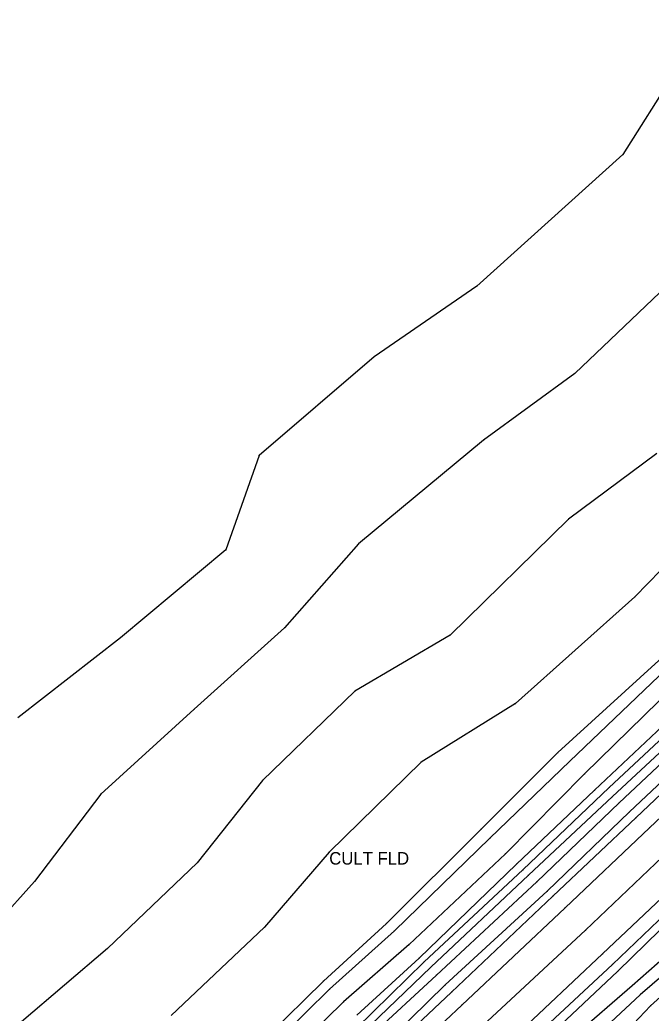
# Model space of a CAD drawing. Extents: x 1419505 to 1434054, y 1956910 to 1968644.
# Drawn here: x 1433102.4 to 1433354.9, y 1967820.7 to 1968218.1 of the extents above; entities that cross this region are included whole.
import ezdxf

# ---------------------------------------------------------------- set-up
doc = ezdxf.new("R2010")
doc.units = 0
for name, color, linetype in [('S_BREAKLINE', 7, 'Continuous'), ('S_DITCHLINE', 7, 'Continuous'), ('S_EDGE_PAVEMENT', 7, 'Continuous'), ('S_GRD_PT_SYM', 7, 'Continuous'), ('S_MSC_PT_SYM', 7, 'Continuous'), ('S_PAVEMENT_CROWN', 7, 'Continuous'), ('S_RDW_PT_SYM', 7, 'Continuous'), ('S_SHOULDER', 7, 'Continuous'), ('S_SURVEY_TEXT_ANNOT', 7, 'Continuous')]:
    doc.layers.add(name, color=color, linetype=linetype)

msp = doc.modelspace()

# ---------------------------------------------------------------- linework, layer by layer
at = {"layer": 'S_BREAKLINE'}
for p, q in [((1433377.4761, 1968218.0776), (1433343.6299, 1968164.1561)), ((1433343.6299, 1968164.1561), (1433285.2201, 1968111.5567)), ((1433372.3288, 1968122.4084), (1433324.3727, 1968076.6374)), ((1433285.2201, 1968111.5567), (1433244.1035, 1968083.3359)), ((1433244.1035, 1968083.3359), (1433198.2095, 1968043.8323)), ((1433324.3727, 1968076.6374), (1433287.8633, 1968049.8817)), ((1433287.8633, 1968049.8817), (1433237.8061, 1968008.441)), ((1433198.2095, 1968043.8323), (1433184.8366, 1968006.0259)), ((1433357.1698, 1968044.5593), (1433321.8795, 1968018.3507)), ((1433381.3473, 1968021.4289), (1433348.4512, 1967987.2566)), ((1433321.8795, 1968018.3507), (1433274.4954, 1967971.9817)), ((1433237.8061, 1968008.441), (1433208.2482, 1967974.8618)), ((1433184.8366, 1968006.0259), (1433142.6609, 1967970.8926)), ((1433348.4512, 1967987.2566), (1433300.7111, 1967944.5899)), ((1433208.2482, 1967974.8618), (1433172.1358, 1967942.2717)), ((1433274.4954, 1967971.9817), (1433236.462, 1967949.5352)), ((1433142.6609, 1967970.8926), (1433101.6873, 1967938.8085)), ((1433366.0013, 1967969.1485), (1433317.6282, 1967925.0046)), ((1433369.0245, 1967966.1193), (1433322.3975, 1967921.5484)), ((1433374.0349, 1967961.366), (1433328.2779, 1967916.4151)), ((1433380.4183, 1967955.4326), (1433332.3222, 1967909.8727)), ((1433236.462, 1967949.5352), (1433199.4326, 1967913.7389)), ((1433388.6688, 1967948.7392), (1433342.1288, 1967904.9293)), ((1433300.7111, 1967944.5899), (1433262.9267, 1967921.1794)), ((1433391.915, 1967944.5839), (1433346.3081, 1967901.2751)), ((1433172.1358, 1967942.2717), (1433134.7944, 1967908.3576)), ((1433317.6282, 1967925.0046), (1433286.9092, 1967894.2976)), ((1433262.9267, 1967921.1794), (1433226.1713, 1967885.1601)), ((1433322.3975, 1967921.5484), (1433290.4185, 1967890.7124)), ((1433328.2779, 1967916.4151), (1433296.6219, 1967884.508)), ((1433199.4326, 1967913.7389), (1433173.3439, 1967880.8768)), ((1433134.7944, 1967908.3576), (1433108.2867, 1967873.3333)), ((1433332.3222, 1967909.8727), (1433300.9981, 1967880.3407)), ((1433342.1288, 1967904.9293), (1433309.2207, 1967873.2893)), ((1433346.3081, 1967901.2751), (1433313.3629, 1967869.469)), ((1433286.9092, 1967894.2976), (1433249.0298, 1967856.6152)), ((1433290.4185, 1967890.7124), (1433252.272, 1967853.717)), ((1433226.1713, 1967885.1601), (1433200.3416, 1967855.1111)), ((1433296.6219, 1967884.508), (1433258.1904, 1967848.1787)), ((1433173.3439, 1967880.8768), (1433137.4226, 1967846.5776)), ((1433300.9981, 1967880.3407), (1433262.1536, 1967842.7623)), ((1433108.2867, 1967873.3333), (1433085.1902, 1967847.7066)), ((1433309.2207, 1967873.2893), (1433269.0291, 1967835.9779)), ((1433313.3629, 1967869.469), (1433272.5963, 1967831.9996)), ((1433376.682, 1967872.0092), (1433341.5898, 1967837.497)), ((1433389.4409, 1967868.772), (1433347.3031, 1967831.6846)), ((1433200.3416, 1967855.1111), (1433162.9732, 1967819.7808)), ((1433249.0298, 1967856.6152), (1433223.8082, 1967833.5837)), ((1433252.272, 1967853.717), (1433226.3333, 1967830.2745)), ((1433137.4226, 1967846.5776), (1433103.1444, 1967817.3197)), ((1433258.1904, 1967848.1787), (1433231.9147, 1967825.2392)), ((1433262.1536, 1967842.7623), (1433237.159, 1967819.8888)), ((1433341.5898, 1967837.497), (1433301.9652, 1967800.2766)), ((1433223.8082, 1967833.5837), (1433186.5128, 1967796.8904)), ((1433269.0291, 1967835.9779), (1433241.2773, 1967810.3682)), ((1433226.3333, 1967830.2745), (1433189.1059, 1967793.8502)), ((1433272.5963, 1967831.9996), (1433246.4166, 1967806.522)), ((1433347.3031, 1967831.6846), (1433305.7615, 1967795.7433)), ((1433231.9147, 1967825.2392), (1433196.1504, 1967790.3909))]:
    msp.add_line(p, q, dxfattribs=at)
at = {"layer": 'S_DITCHLINE'}
for p, q in [((1433383.1975, 1967953.1234), (1433338.1335, 1967910.9367)), ((1433386.0926, 1967950.9283), (1433339.4866, 1967907.3875)), ((1433338.1335, 1967910.9367), (1433303.6153, 1967878.0406)), ((1433339.4866, 1967907.3875), (1433305.9285, 1967875.9555)), ((1433303.6153, 1967878.0406), (1433264.0878, 1967841.2452)), ((1433305.9285, 1967875.9555), (1433266.7869, 1967839.1381)), ((1433392.5861, 1967864.4477), (1433350.4883, 1967828.0614)), ((1433395.8103, 1967860.7865), (1433354.6046, 1967823.5971)), ((1433264.0878, 1967841.2452), (1433236.969, 1967814.5745)), ((1433266.7869, 1967839.1381), (1433239.2612, 1967812.6364)), ((1433350.4883, 1967828.0614), (1433309.1797, 1967789.6279)), ((1433354.6046, 1967823.5971), (1433316.6672, 1967783.7655))]:
    msp.add_line(p, q, dxfattribs=at)
at = {"layer": 'S_EDGE_PAVEMENT'}
for p, q in [((1433399.6665, 1967938.1975), (1433354.2296, 1967894.8497)), ((1433354.2296, 1967894.8497), (1433320.4914, 1967862.8816)), ((1433370.7557, 1967877.9586), (1433335.4914, 1967844.4224)), ((1433320.4914, 1967862.8816), (1433279.1627, 1967823.9671)), ((1433335.4914, 1967844.4224), (1433295.3648, 1967806.742)), ((1433279.1627, 1967823.9671), (1433253.037, 1967799.2915))]:
    msp.add_line(p, q, dxfattribs=at)
at = {"layer": 'S_GRD_PT_SYM'}
for points in [[(1433343.6299, 1968164.1561), (1433343.6299, 1968164.2061), (1433343.6299, 1968164.1561), (1433343.5799, 1968164.1561), (1433343.6299, 1968164.1561), (1433343.6299, 1968164.1061), (1433343.6299, 1968164.1561), (1433343.6799, 1968164.1561)], [(1433285.2201, 1968111.5567), (1433285.2201, 1968111.6067), (1433285.2201, 1968111.5567), (1433285.1701, 1968111.5567), (1433285.2201, 1968111.5567), (1433285.2201, 1968111.5067), (1433285.2201, 1968111.5567), (1433285.2701, 1968111.5567)], [(1433244.1035, 1968083.3359), (1433244.1035, 1968083.3859), (1433244.1035, 1968083.3359), (1433244.0535, 1968083.3359), (1433244.1035, 1968083.3359), (1433244.1035, 1968083.2859), (1433244.1035, 1968083.3359), (1433244.1535, 1968083.3359)], [(1433324.3727, 1968076.6374), (1433324.3727, 1968076.6874), (1433324.3727, 1968076.6374), (1433324.3227, 1968076.6374), (1433324.3727, 1968076.6374), (1433324.3727, 1968076.5874), (1433324.3727, 1968076.6374), (1433324.4227, 1968076.6374)], [(1433287.8633, 1968049.8817), (1433287.8633, 1968049.9317), (1433287.8633, 1968049.8817), (1433287.8133, 1968049.8817), (1433287.8633, 1968049.8817), (1433287.8633, 1968049.8317), (1433287.8633, 1968049.8817), (1433287.9133, 1968049.8817)], [(1433198.2095, 1968043.8323), (1433198.2095, 1968043.8823), (1433198.2095, 1968043.8323), (1433198.1595, 1968043.8323), (1433198.2095, 1968043.8323), (1433198.2095, 1968043.7823), (1433198.2095, 1968043.8323), (1433198.2595, 1968043.8323)], [(1433321.8795, 1968018.3507), (1433321.8795, 1968018.4007), (1433321.8795, 1968018.3507), (1433321.8295, 1968018.3507), (1433321.8795, 1968018.3507), (1433321.8795, 1968018.3007), (1433321.8795, 1968018.3507), (1433321.9295, 1968018.3507)], [(1433237.8061, 1968008.441), (1433237.8061, 1968008.491), (1433237.8061, 1968008.441), (1433237.7561, 1968008.441), (1433237.8061, 1968008.441), (1433237.8061, 1968008.391), (1433237.8061, 1968008.441), (1433237.8561, 1968008.441)], [(1433184.8366, 1968006.0259), (1433184.8366, 1968006.0759), (1433184.8366, 1968006.0259), (1433184.7866, 1968006.0259), (1433184.8366, 1968006.0259), (1433184.8366, 1968005.9759), (1433184.8366, 1968006.0259), (1433184.8866, 1968006.0259)], [(1433348.4512, 1967987.2566), (1433348.4512, 1967987.3066), (1433348.4512, 1967987.2566), (1433348.4012, 1967987.2566), (1433348.4512, 1967987.2566), (1433348.4512, 1967987.2066), (1433348.4512, 1967987.2566), (1433348.5012, 1967987.2566)], [(1433208.2482, 1967974.8618), (1433208.2482, 1967974.9118), (1433208.2482, 1967974.8618), (1433208.1982, 1967974.8618), (1433208.2482, 1967974.8618), (1433208.2482, 1967974.8118), (1433208.2482, 1967974.8618), (1433208.2982, 1967974.8618)], [(1433274.4954, 1967971.9817), (1433274.4954, 1967972.0317), (1433274.4954, 1967971.9817), (1433274.4454, 1967971.9817), (1433274.4954, 1967971.9817), (1433274.4954, 1967971.9317), (1433274.4954, 1967971.9817), (1433274.5454, 1967971.9817)], [(1433142.6609, 1967970.8926), (1433142.6609, 1967970.9426), (1433142.6609, 1967970.8926), (1433142.6109, 1967970.8926), (1433142.6609, 1967970.8926), (1433142.6609, 1967970.8426), (1433142.6609, 1967970.8926), (1433142.7109, 1967970.8926)], [(1433236.462, 1967949.5352), (1433236.462, 1967949.5852), (1433236.462, 1967949.5352), (1433236.412, 1967949.5352), (1433236.462, 1967949.5352), (1433236.462, 1967949.4852), (1433236.462, 1967949.5352), (1433236.512, 1967949.5352)], [(1433300.7111, 1967944.5899), (1433300.7111, 1967944.6399), (1433300.7111, 1967944.5899), (1433300.6611, 1967944.5899), (1433300.7111, 1967944.5899), (1433300.7111, 1967944.5399), (1433300.7111, 1967944.5899), (1433300.7611, 1967944.5899)], [(1433172.1358, 1967942.2717), (1433172.1358, 1967942.3217), (1433172.1358, 1967942.2717), (1433172.0858, 1967942.2717), (1433172.1358, 1967942.2717), (1433172.1358, 1967942.2217), (1433172.1358, 1967942.2717), (1433172.1858, 1967942.2717)], [(1433317.6282, 1967925.0046), (1433317.6282, 1967925.0546), (1433317.6282, 1967925.0046), (1433317.5782, 1967925.0046), (1433317.6282, 1967925.0046), (1433317.6282, 1967924.9546), (1433317.6282, 1967925.0046), (1433317.6782, 1967925.0046)], [(1433262.9267, 1967921.1794), (1433262.9267, 1967921.2294), (1433262.9267, 1967921.1794), (1433262.8767, 1967921.1794), (1433262.9267, 1967921.1794), (1433262.9267, 1967921.1294), (1433262.9267, 1967921.1794), (1433262.9767, 1967921.1794)], [(1433322.3975, 1967921.5484), (1433322.3975, 1967921.5984), (1433322.3975, 1967921.5484), (1433322.3475, 1967921.5484), (1433322.3975, 1967921.5484), (1433322.3975, 1967921.4984), (1433322.3975, 1967921.5484), (1433322.4475, 1967921.5484)], [(1433328.2779, 1967916.4151), (1433328.2779, 1967916.4651), (1433328.2779, 1967916.4151), (1433328.2279, 1967916.4151), (1433328.2779, 1967916.4151), (1433328.2779, 1967916.3651), (1433328.2779, 1967916.4151), (1433328.3279, 1967916.4151)], [(1433199.4326, 1967913.7389), (1433199.4326, 1967913.7889), (1433199.4326, 1967913.7389), (1433199.3826, 1967913.7389), (1433199.4326, 1967913.7389), (1433199.4326, 1967913.6889), (1433199.4326, 1967913.7389), (1433199.4826, 1967913.7389)], [(1433134.7944, 1967908.3576), (1433134.7944, 1967908.4076), (1433134.7944, 1967908.3576), (1433134.7444, 1967908.3576), (1433134.7944, 1967908.3576), (1433134.7944, 1967908.3076), (1433134.7944, 1967908.3576), (1433134.8444, 1967908.3576)], [(1433332.3222, 1967909.8727), (1433332.3222, 1967909.9227), (1433332.3222, 1967909.8727), (1433332.2722, 1967909.8727), (1433332.3222, 1967909.8727), (1433332.3222, 1967909.8227), (1433332.3222, 1967909.8727), (1433332.3722, 1967909.8727)], [(1433338.1335, 1967910.9367), (1433338.1335, 1967910.9867), (1433338.1335, 1967910.9367), (1433338.0835, 1967910.9367), (1433338.1335, 1967910.9367), (1433338.1335, 1967910.8867), (1433338.1335, 1967910.9367), (1433338.1835, 1967910.9367)], [(1433339.4866, 1967907.3875), (1433339.4866, 1967907.4375), (1433339.4866, 1967907.3875), (1433339.4366, 1967907.3875), (1433339.4866, 1967907.3875), (1433339.4866, 1967907.3375), (1433339.4866, 1967907.3875), (1433339.5366, 1967907.3875)], [(1433342.1288, 1967904.9293), (1433342.1288, 1967904.9793), (1433342.1288, 1967904.9293), (1433342.0788, 1967904.9293), (1433342.1288, 1967904.9293), (1433342.1288, 1967904.8793), (1433342.1288, 1967904.9293), (1433342.1788, 1967904.9293)], [(1433346.3081, 1967901.2751), (1433346.3081, 1967901.3251), (1433346.3081, 1967901.2751), (1433346.2581, 1967901.2751), (1433346.3081, 1967901.2751), (1433346.3081, 1967901.2251), (1433346.3081, 1967901.2751), (1433346.3581, 1967901.2751)], [(1433286.9092, 1967894.2976), (1433286.9092, 1967894.3476), (1433286.9092, 1967894.2976), (1433286.8592, 1967894.2976), (1433286.9092, 1967894.2976), (1433286.9092, 1967894.2476), (1433286.9092, 1967894.2976), (1433286.9592, 1967894.2976)], [(1433290.4185, 1967890.7124), (1433290.4185, 1967890.7624), (1433290.4185, 1967890.7124), (1433290.3685, 1967890.7124), (1433290.4185, 1967890.7124), (1433290.4185, 1967890.6624), (1433290.4185, 1967890.7124), (1433290.4685, 1967890.7124)], [(1433226.1713, 1967885.1601), (1433226.1713, 1967885.2101), (1433226.1713, 1967885.1601), (1433226.1213, 1967885.1601), (1433226.1713, 1967885.1601), (1433226.1713, 1967885.1101), (1433226.1713, 1967885.1601), (1433226.2213, 1967885.1601)], [(1433296.6219, 1967884.508), (1433296.6219, 1967884.558), (1433296.6219, 1967884.508), (1433296.5719, 1967884.508), (1433296.6219, 1967884.508), (1433296.6219, 1967884.458), (1433296.6219, 1967884.508), (1433296.6719, 1967884.508)], [(1433173.3439, 1967880.8768), (1433173.3439, 1967880.9268), (1433173.3439, 1967880.8768), (1433173.2939, 1967880.8768), (1433173.3439, 1967880.8768), (1433173.3439, 1967880.8268), (1433173.3439, 1967880.8768), (1433173.3939, 1967880.8768)], [(1433300.9981, 1967880.3407), (1433300.9981, 1967880.3907), (1433300.9981, 1967880.3407), (1433300.9481, 1967880.3407), (1433300.9981, 1967880.3407), (1433300.9981, 1967880.2907), (1433300.9981, 1967880.3407), (1433301.0481, 1967880.3407)], [(1433303.6153, 1967878.0406), (1433303.6153, 1967878.0906), (1433303.6153, 1967878.0406), (1433303.5653, 1967878.0406), (1433303.6153, 1967878.0406), (1433303.6153, 1967877.9906), (1433303.6153, 1967878.0406), (1433303.6653, 1967878.0406)], [(1433108.2867, 1967873.3333), (1433108.2867, 1967873.3833), (1433108.2867, 1967873.3333), (1433108.2367, 1967873.3333), (1433108.2867, 1967873.3333), (1433108.2867, 1967873.2833), (1433108.2867, 1967873.3333), (1433108.3367, 1967873.3333)], [(1433305.9285, 1967875.9555), (1433305.9285, 1967876.0055), (1433305.9285, 1967875.9555), (1433305.8785, 1967875.9555), (1433305.9285, 1967875.9555), (1433305.9285, 1967875.9055), (1433305.9285, 1967875.9555), (1433305.9785, 1967875.9555)], [(1433309.2207, 1967873.2893), (1433309.2207, 1967873.3393), (1433309.2207, 1967873.2893), (1433309.1707, 1967873.2893), (1433309.2207, 1967873.2893), (1433309.2207, 1967873.2393), (1433309.2207, 1967873.2893), (1433309.2707, 1967873.2893)], [(1433313.3629, 1967869.469), (1433313.3629, 1967869.519), (1433313.3629, 1967869.469), (1433313.3129, 1967869.469), (1433313.3629, 1967869.469), (1433313.3629, 1967869.419), (1433313.3629, 1967869.469), (1433313.4129, 1967869.469)], [(1433249.0298, 1967856.6152), (1433249.0298, 1967856.6652), (1433249.0298, 1967856.6152), (1433248.9798, 1967856.6152), (1433249.0298, 1967856.6152), (1433249.0298, 1967856.5652), (1433249.0298, 1967856.6152), (1433249.0798, 1967856.6152)], [(1433200.3416, 1967855.1111), (1433200.3416, 1967855.1611), (1433200.3416, 1967855.1111), (1433200.2916, 1967855.1111), (1433200.3416, 1967855.1111), (1433200.3416, 1967855.0611), (1433200.3416, 1967855.1111), (1433200.3916, 1967855.1111)], [(1433252.272, 1967853.717), (1433252.272, 1967853.767), (1433252.272, 1967853.717), (1433252.222, 1967853.717), (1433252.272, 1967853.717), (1433252.272, 1967853.667), (1433252.272, 1967853.717), (1433252.322, 1967853.717)], [(1433137.4226, 1967846.5776), (1433137.4226, 1967846.6276), (1433137.4226, 1967846.5776), (1433137.3726, 1967846.5776), (1433137.4226, 1967846.5776), (1433137.4226, 1967846.5276), (1433137.4226, 1967846.5776), (1433137.4726, 1967846.5776)], [(1433258.1904, 1967848.1787), (1433258.1904, 1967848.2287), (1433258.1904, 1967848.1787), (1433258.1404, 1967848.1787), (1433258.1904, 1967848.1787), (1433258.1904, 1967848.1287), (1433258.1904, 1967848.1787), (1433258.2404, 1967848.1787)], [(1433262.1536, 1967842.7623), (1433262.1536, 1967842.8123), (1433262.1536, 1967842.7623), (1433262.1036, 1967842.7623), (1433262.1536, 1967842.7623), (1433262.1536, 1967842.7123), (1433262.1536, 1967842.7623), (1433262.2036, 1967842.7623)], [(1433264.0878, 1967841.2452), (1433264.0878, 1967841.2952), (1433264.0878, 1967841.2452), (1433264.0378, 1967841.2452), (1433264.0878, 1967841.2452), (1433264.0878, 1967841.1952), (1433264.0878, 1967841.2452), (1433264.1378, 1967841.2452)], [(1433266.7869, 1967839.1381), (1433266.7869, 1967839.1881), (1433266.7869, 1967839.1381), (1433266.7369, 1967839.1381), (1433266.7869, 1967839.1381), (1433266.7869, 1967839.0881), (1433266.7869, 1967839.1381), (1433266.8369, 1967839.1381)], [(1433341.5898, 1967837.497), (1433341.5898, 1967837.547), (1433341.5898, 1967837.497), (1433341.5398, 1967837.497), (1433341.5898, 1967837.497), (1433341.5898, 1967837.447), (1433341.5898, 1967837.497), (1433341.6398, 1967837.497)], [(1433223.8082, 1967833.5837), (1433223.8082, 1967833.6337), (1433223.8082, 1967833.5837), (1433223.7582, 1967833.5837), (1433223.8082, 1967833.5837), (1433223.8082, 1967833.5337), (1433223.8082, 1967833.5837), (1433223.8582, 1967833.5837)], [(1433269.0291, 1967835.9779), (1433269.0291, 1967836.0279), (1433269.0291, 1967835.9779), (1433268.9791, 1967835.9779), (1433269.0291, 1967835.9779), (1433269.0291, 1967835.9279), (1433269.0291, 1967835.9779), (1433269.0791, 1967835.9779)], [(1433226.3333, 1967830.2745), (1433226.3333, 1967830.3245), (1433226.3333, 1967830.2745), (1433226.2833, 1967830.2745), (1433226.3333, 1967830.2745), (1433226.3333, 1967830.2245), (1433226.3333, 1967830.2745), (1433226.3833, 1967830.2745)], [(1433272.5963, 1967831.9996), (1433272.5963, 1967832.0496), (1433272.5963, 1967831.9996), (1433272.5463, 1967831.9996), (1433272.5963, 1967831.9996), (1433272.5963, 1967831.9496), (1433272.5963, 1967831.9996), (1433272.6463, 1967831.9996)], [(1433347.3031, 1967831.6846), (1433347.3031, 1967831.7346), (1433347.3031, 1967831.6846), (1433347.2531, 1967831.6846), (1433347.3031, 1967831.6846), (1433347.3031, 1967831.6346), (1433347.3031, 1967831.6846), (1433347.3531, 1967831.6846)], [(1433231.9147, 1967825.2392), (1433231.9147, 1967825.2892), (1433231.9147, 1967825.2392), (1433231.8647, 1967825.2392), (1433231.9147, 1967825.2392), (1433231.9147, 1967825.1892), (1433231.9147, 1967825.2392), (1433231.9647, 1967825.2392)], [(1433350.4883, 1967828.0614), (1433350.4883, 1967828.1114), (1433350.4883, 1967828.0614), (1433350.4383, 1967828.0614), (1433350.4883, 1967828.0614), (1433350.4883, 1967828.0114), (1433350.4883, 1967828.0614), (1433350.5383, 1967828.0614)], [(1433354.6046, 1967823.5971), (1433354.6046, 1967823.6471), (1433354.6046, 1967823.5971), (1433354.5546, 1967823.5971), (1433354.6046, 1967823.5971), (1433354.6046, 1967823.5471), (1433354.6046, 1967823.5971), (1433354.6546, 1967823.5971)]]:
    msp.add_lwpolyline(points, dxfattribs=at)
at = {"layer": 'S_MSC_PT_SYM'}
msp.add_lwpolyline([(1433226.1713, 1967885.1601), (1433226.1713, 1967885.2101), (1433226.1713, 1967885.1601), (1433226.1213, 1967885.1601), (1433226.1713, 1967885.1601), (1433226.1713, 1967885.1101), (1433226.1713, 1967885.1601), (1433226.2213, 1967885.1601)], dxfattribs=at)
at = {"layer": 'S_PAVEMENT_CROWN'}
for p, q in [((1433362.3101, 1967885.9091), (1433328.6849, 1967853.869)), ((1433328.6849, 1967853.869), (1433287.6343, 1967815.8096))]:
    msp.add_line(p, q, dxfattribs=at)
at = {"layer": 'S_RDW_PT_SYM'}
for points in [[(1433348.9792, 1967899.06), (1433348.9792, 1967899.11), (1433348.9792, 1967899.06), (1433348.9292, 1967899.06), (1433348.9792, 1967899.06), (1433348.9792, 1967899.01), (1433348.9792, 1967899.06), (1433349.0292, 1967899.06)], [(1433354.2296, 1967894.8497), (1433354.2296, 1967894.8997), (1433354.2296, 1967894.8497), (1433354.1796, 1967894.8497), (1433354.2296, 1967894.8497), (1433354.2296, 1967894.7997), (1433354.2296, 1967894.8497), (1433354.2796, 1967894.8497)], [(1433315.6171, 1967867.5559), (1433315.6171, 1967867.6059), (1433315.6171, 1967867.5559), (1433315.5671, 1967867.5559), (1433315.6171, 1967867.5559), (1433315.6171, 1967867.5059), (1433315.6171, 1967867.5559), (1433315.6671, 1967867.5559)], [(1433320.4914, 1967862.8816), (1433320.4914, 1967862.9316), (1433320.4914, 1967862.8816), (1433320.4414, 1967862.8816), (1433320.4914, 1967862.8816), (1433320.4914, 1967862.8316), (1433320.4914, 1967862.8816), (1433320.5414, 1967862.8816)], [(1433328.6849, 1967853.869), (1433328.6849, 1967853.919), (1433328.6849, 1967853.869), (1433328.6349, 1967853.869), (1433328.6849, 1967853.869), (1433328.6849, 1967853.819), (1433328.6849, 1967853.869), (1433328.7349, 1967853.869)], [(1433335.4914, 1967844.4224), (1433335.4914, 1967844.4724), (1433335.4914, 1967844.4224), (1433335.4414, 1967844.4224), (1433335.4914, 1967844.4224), (1433335.4914, 1967844.3724), (1433335.4914, 1967844.4224), (1433335.5414, 1967844.4224)], [(1433339.4096, 1967840.2142), (1433339.4096, 1967840.2642), (1433339.4096, 1967840.2142), (1433339.3596, 1967840.2142), (1433339.4096, 1967840.2142), (1433339.4096, 1967840.1642), (1433339.4096, 1967840.2142), (1433339.4596, 1967840.2142)], [(1433275.0165, 1967829.0924), (1433275.0165, 1967829.1424), (1433275.0165, 1967829.0924), (1433274.9665, 1967829.0924), (1433275.0165, 1967829.0924), (1433275.0165, 1967829.0424), (1433275.0165, 1967829.0924), (1433275.0665, 1967829.0924)], [(1433279.1627, 1967823.9671), (1433279.1627, 1967824.0171), (1433279.1627, 1967823.9671), (1433279.1127, 1967823.9671), (1433279.1627, 1967823.9671), (1433279.1627, 1967823.9171), (1433279.1627, 1967823.9671), (1433279.2127, 1967823.9671)]]:
    msp.add_lwpolyline(points, dxfattribs=at)
at = {"layer": 'S_SHOULDER'}
for p, q in [((1433394.5702, 1967942.3597), (1433348.9792, 1967899.06)), ((1433348.9792, 1967899.06), (1433315.6171, 1967867.5559)), ((1433374.7049, 1967873.9903), (1433339.4096, 1967840.2142)), ((1433315.6171, 1967867.5559), (1433275.0165, 1967829.0924)), ((1433339.4096, 1967840.2142), (1433298.793, 1967802.4297)), ((1433275.0165, 1967829.0924), (1433248.3907, 1967804.0478))]:
    msp.add_line(p, q, dxfattribs=at)

# ---------------------------------------------------------------- texts
at = {"layer": 'S_SURVEY_TEXT_ANNOT'}
msp.add_text('CULT FLD', height=5, dxfattribs=at).set_placement((1433226.1713, 1967880.1601))

doc.saveas('drawing.dxf')
